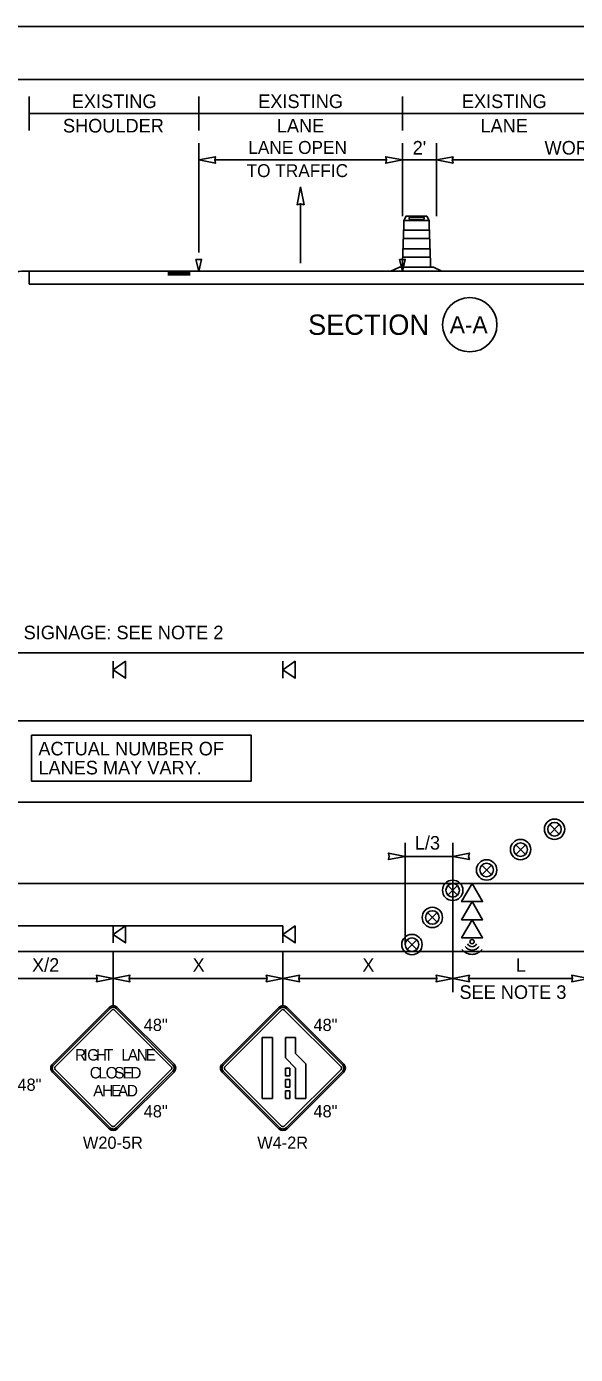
# Model space of a CAD drawing. Extents: x 99999 to 100116, y 99995 to 100013.
# Drawn here: x 100004.26 to 100007.5, y 100002.86 to 100010.69 of the extents above; entities that cross this region are included whole.
import ezdxf

# ---------------------------------------------------------------- set-up
doc = ezdxf.new("R2010")
doc.units = 0
for name, color, linetype in [('RD_ED_ShoulderPavedEdge', 7, 'Continuous'), ('RD_MK_LineEdgeWhite', 7, 'Continuous'), ('RD_MK_LineEdgeYellow', 7, 'Continuous'), ('RD_MK_LineLane', 7, 'Continuous'), ('SH_GI_PlotLimits', 7, 'Continuous'), ('SH_GI_SheetBorder', 7, 'Continuous'), ('SH_TI_Tables', 7, 'Continuous'), ('SH_TI_WZSectionCut', 7, 'Continuous'), ('TR_SN_ConstructionSigns', 7, 'Continuous'), ('TR_WZ_ArrowLeftStrRightTurn', 7, 'Continuous'), ('TR_WZ_PortableSignMountBlk-Org', 7, 'Continuous'), ('TR_WZ_SequentialArrowSign', 7, 'Continuous'), ('TR_WZ_TrafficSafetyDrum', 7, 'Continuous'), ('TR_WZ_TrafficSafetyDrumElev', 7, 'Continuous'), ('TR_WZ_WorkZoneDetails', 7, 'Continuous'), ('TR_WZ_WorkZoneTextCurrent', 7, 'Continuous')]:
    doc.layers.add(name, color=color, linetype=linetype)

msp = doc.modelspace()

# ---------------------------------------------------------------- linework, layer by layer
at = {"layer": 'RD_ED_ShoulderPavedEdge'}
for p, q in [((100000.8283, 100006.9957), (100015.62, 100006.9957)), ((100000.8283, 100005.2357), (100015.62, 100005.2357))]:
    msp.add_line(p, q, dxfattribs=at)
at = {"layer": 'RD_MK_LineEdgeWhite'}
msp.add_line((100000.8283, 100005.6357), (100015.62, 100005.6357), dxfattribs=at)
at = {"layer": 'RD_MK_LineEdgeYellow'}
msp.add_line((100000.8283, 100006.5957), (100015.62, 100006.5957), dxfattribs=at)
at = {"layer": 'RD_MK_LineLane'}
msp.add_lwpolyline([(100015.62, 100006.1157), (100000.8283, 100006.1157)], dxfattribs=at)
at = {"layer": 'SH_GI_PlotLimits'}
msp.add_lwpolyline([(99999.0625, 99999.6875), (100016.0625, 99999.6875), (100016.0625, 100010.6875), (99999.0625, 100010.6875)], close=True, dxfattribs=at)
at = {"layer": 'SH_GI_SheetBorder'}
msp.add_line((100000, 100010.375), (100015.75, 100010.375), dxfattribs=at)
at = {"layer": 'SH_TI_Tables'}
msp.add_lwpolyline([(100004.2941, 100006.511), (100005.5872, 100006.511), (100005.5872, 100006.239), (100004.2941, 100006.239)], close=True, dxfattribs=at)
at = {"layer": 'SH_TI_WZSectionCut'}
for p, q in [((100004.2794, 100010.075), (100004.2794, 100010.275)), ((100005.2794, 100010.075), (100005.2794, 100010.275)), ((100006.4794, 100010.075), (100006.4794, 100010.275)), ((100004.2794, 100010.175), (100005.2794, 100010.175)), ((100005.2794, 100010.175), (100006.4794, 100010.175)), ((100006.4794, 100010.175), (100007.6794, 100010.175)), ((100005.2794, 100009.3547), (100005.2794, 100010.001)), ((100006.4794, 100009.57), (100006.4794, 100010.001)), ((100006.6794, 100009.57), (100006.6794, 100010.001)), ((100005.3731, 100009.901), (100006.3857, 100009.901)), ((100006.4794, 100009.901), (100006.6794, 100009.901)), ((100006.7731, 100009.901), (100008.5857, 100009.901)), ((100004.2794, 100009.2449), (100004.2794, 100009.1699)), ((100008.6794, 100009.2449), (100004.2794, 100009.2449)), ((100005.0964, 100009.2397), (100005.2294, 100009.2397)), ((100005.0964, 100009.2341), (100005.2294, 100009.2341)), ((100005.0964, 100009.2284), (100005.2294, 100009.2284)), ((100008.6794, 100009.1699), (100004.2794, 100009.1699)), ((100005.0964, 100009.2232), (100005.2294, 100009.2232))]:
    msp.add_line(p, q, dxfattribs=at)
for points in [[(100005.2794, 100009.901), (100005.3777, 100009.8817), (100005.3731, 100009.901), (100005.3777, 100009.9203)], [(100006.4794, 100009.901), (100006.3811, 100009.8817), (100006.3857, 100009.901), (100006.3811, 100009.9203)], [(100006.6794, 100009.901), (100006.7777, 100009.8817), (100006.7731, 100009.901), (100006.7777, 100009.9203)], [(100005.2627, 100009.3147), (100005.296, 100009.3147), (100005.2794, 100009.2449)], [(100006.4627, 100009.3147), (100006.4961, 100009.3147), (100006.4794, 100009.2449)]]:
    msp.add_lwpolyline(points, close=True, dxfattribs=at)
msp.add_circle((100006.8759, 100008.93), 0.16, dxfattribs=at)
msp.add_open_spline([(100004.2794, 100009.2449), (100004.0282, 100009.2449), (100003.9027, 100009.1828), (100003.7773, 100009.1828)], degree=2, dxfattribs=at)
at = {"layer": 'TR_SN_ConstructionSigns'}
for p, q in [((100004.7514, 100004.9058), (100004.4173, 100004.5717)), ((100004.7574, 100004.8999), (100004.4233, 100004.5658)), ((100004.4332, 100004.5558), (100004.7673, 100004.8899)), ((100004.7832, 100004.8899), (100005.1173, 100004.5558)), ((100005.1273, 100004.5658), (100004.7932, 100004.8999)), ((100005.1333, 100004.5717), (100004.7991, 100004.9058)), ((100005.7514, 100004.9058), (100005.4173, 100004.5717)), ((100005.7574, 100004.8999), (100005.4233, 100004.5658)), ((100005.4332, 100004.5558), (100005.7673, 100004.8899)), ((100005.7832, 100004.8899), (100006.1173, 100004.5558)), ((100006.1273, 100004.5658), (100005.7932, 100004.8999)), ((100006.1333, 100004.5717), (100005.7991, 100004.9058)), ((100005.6536, 100004.7279), (100005.7141, 100004.7279)), ((100005.6536, 100004.3679), (100005.6536, 100004.7279)), ((100005.7141, 100004.7279), (100005.6536, 100004.7279)), ((100005.6536, 100004.7279), (100005.6536, 100004.3679)), ((100005.7141, 100004.7279), (100005.7141, 100004.3679)), ((100005.7141, 100004.3679), (100005.7141, 100004.7279)), ((100005.7893, 100004.7279), (100005.8498, 100004.7279)), ((100005.7893, 100004.6083), (100005.7893, 100004.7279)), ((100005.8498, 100004.7279), (100005.7893, 100004.7279)), ((100005.7893, 100004.7279), (100005.7893, 100004.6083)), ((100005.8498, 100004.7279), (100005.8498, 100004.6334)), ((100005.8498, 100004.6334), (100005.8498, 100004.7279)), ((100005.8498, 100004.6334), (100005.9103, 100004.5729)), ((100005.9103, 100004.5729), (100005.8498, 100004.6334)), ((100004.7673, 100004.2058), (100004.4332, 100004.5399)), ((100005.1173, 100004.5399), (100004.7832, 100004.2058)), ((100005.7673, 100004.2058), (100005.4332, 100004.5399)), ((100006.1173, 100004.5399), (100005.7832, 100004.2058)), ((100005.8498, 100004.5479), (100005.7893, 100004.6083)), ((100005.7893, 100004.6083), (100005.8498, 100004.5479)), ((100005.7893, 100004.5479), (100005.8161, 100004.5479)), ((100005.7893, 100004.5029), (100005.7893, 100004.5479)), ((100005.8161, 100004.5479), (100005.7893, 100004.5479)), ((100005.7893, 100004.5479), (100005.7893, 100004.5029)), ((100005.8161, 100004.5479), (100005.8161, 100004.5029)), ((100005.8161, 100004.5029), (100005.8161, 100004.5479)), ((100005.8498, 100004.3679), (100005.8498, 100004.5479)), ((100005.8498, 100004.5479), (100005.8498, 100004.3679)), ((100005.9103, 100004.5729), (100005.9103, 100004.3679)), ((100005.9103, 100004.3679), (100005.9103, 100004.5729)), ((100004.4173, 100004.524), (100004.7514, 100004.1899)), ((100004.4233, 100004.53), (100004.7574, 100004.1959)), ((100004.7932, 100004.1959), (100005.1273, 100004.53)), ((100004.7991, 100004.1899), (100005.1333, 100004.524)), ((100005.4173, 100004.524), (100005.7514, 100004.1899)), ((100005.4233, 100004.53), (100005.7574, 100004.1959)), ((100005.8161, 100004.5029), (100005.7893, 100004.5029)), ((100005.7893, 100004.5029), (100005.8161, 100004.5029)), ((100005.7893, 100004.4804), (100005.8161, 100004.4804)), ((100005.7893, 100004.4354), (100005.7893, 100004.4804)), ((100005.8161, 100004.4804), (100005.7893, 100004.4804)), ((100005.7893, 100004.4804), (100005.7893, 100004.4354)), ((100005.7932, 100004.1959), (100006.1273, 100004.53)), ((100005.7991, 100004.1899), (100006.1333, 100004.524)), ((100005.8161, 100004.4804), (100005.8161, 100004.4354)), ((100005.8161, 100004.4354), (100005.8161, 100004.4804)), ((100005.8161, 100004.4354), (100005.7893, 100004.4354)), ((100005.7893, 100004.4354), (100005.8161, 100004.4354)), ((100005.7893, 100004.4129), (100005.8161, 100004.4129)), ((100005.7893, 100004.3679), (100005.7893, 100004.4129)), ((100005.8161, 100004.4129), (100005.7893, 100004.4129)), ((100005.7893, 100004.4129), (100005.7893, 100004.3679)), ((100005.8161, 100004.4129), (100005.8161, 100004.3679)), ((100005.8161, 100004.3679), (100005.8161, 100004.4129)), ((100005.7141, 100004.3679), (100005.6536, 100004.3679)), ((100005.6536, 100004.3679), (100005.7141, 100004.3679)), ((100005.8161, 100004.3679), (100005.7893, 100004.3679)), ((100005.7893, 100004.3679), (100005.8161, 100004.3679)), ((100005.9103, 100004.3679), (100005.8498, 100004.3679)), ((100005.8498, 100004.3679), (100005.9103, 100004.3679))]:
    msp.add_line(p, q, dxfattribs=at)
for centre, radius, start, end in [((100004.7753, 100004.882), 0.0338, 45, 135), ((100004.7753, 100004.882), 0.0253, 45, 135), ((100004.7753, 100004.882), 0.0113, 45, 135), ((100005.7753, 100004.882), 0.0338, 45, 135), ((100005.7753, 100004.882), 0.0253, 45, 135), ((100005.7753, 100004.882), 0.0113, 45, 135), ((100004.4412, 100004.5479), 0.0338, 135, 225.00001), ((100004.4412, 100004.5479), 0.0253, 135, 225.00001), ((100004.4412, 100004.5479), 0.0113, 135, 225.00001), ((100005.1094, 100004.5479), 0.0113, 315.00002, 45), ((100005.1094, 100004.5479), 0.0253, 315.00002, 45), ((100005.1094, 100004.5479), 0.0338, 315.00001, 45.00001), ((100005.4412, 100004.5479), 0.0338, 135, 225.00001), ((100005.4412, 100004.5479), 0.0253, 135, 225.00001), ((100005.4412, 100004.5479), 0.0113, 135, 225.00001), ((100006.1094, 100004.5479), 0.0113, 315.00002, 45), ((100006.1094, 100004.5479), 0.0253, 315.00002, 45), ((100006.1094, 100004.5479), 0.0338, 315.00001, 45.00001), ((100004.7753, 100004.2138), 0.0338, 225.00001, 315.00001), ((100004.7753, 100004.2138), 0.0253, 225.00001, 315.00002), ((100004.7753, 100004.2138), 0.0113, 225.00001, 315.00002), ((100005.7753, 100004.2138), 0.0338, 225.00001, 315.00001), ((100005.7753, 100004.2138), 0.0253, 225.00001, 315.00002), ((100005.7753, 100004.2138), 0.0113, 225.00001, 315.00002)]:
    msp.add_arc(centre, radius, start, end, dxfattribs=at)
at = {"layer": 'TR_WZ_ArrowLeftStrRightTurn'}
msp.add_line((100005.8794, 100009.6418), (100005.8794, 100009.292), dxfattribs=at)
msp.add_lwpolyline([(100005.8794, 100009.742), (100005.8588, 100009.6369), (100005.8794, 100009.6418), (100005.9, 100009.6369)], close=True, dxfattribs=at)
at = {"layer": 'TR_WZ_PortableSignMountBlk-Org'}
for p, q in [((100004.7753, 100006.8458), (100004.7753, 100006.9458)), ((100005.7753, 100006.8458), (100005.7753, 100006.9458)), ((100004.7753, 100005.2858), (100004.7753, 100005.3858)), ((100005.7753, 100005.2858), (100005.7753, 100005.3858))]:
    msp.add_line(p, q, dxfattribs=at)
for points in [[(100004.7753, 100006.8957), (100004.8471, 100006.9458), (100004.8471, 100006.8458)], [(100005.7753, 100006.8957), (100005.8471, 100006.9458), (100005.8471, 100006.8458)], [(100004.7753, 100005.3357), (100004.8471, 100005.3858), (100004.8471, 100005.2858)], [(100005.7753, 100005.3357), (100005.8471, 100005.3858), (100005.8471, 100005.2858)]]:
    msp.add_lwpolyline(points, close=True, dxfattribs=at)
at = {"layer": 'TR_WZ_SequentialArrowSign'}
for points in [[(100006.8895, 100005.6357), (100006.8278, 100005.5291), (100006.8895, 100005.5291), (100006.9513, 100005.5291), (100006.8895, 100005.6357)], [(100006.9513, 100005.5291), (100006.8895, 100005.5291), (100006.8278, 100005.5291), (100006.8895, 100005.6357), (100006.9513, 100005.5291)], [(100006.8895, 100005.5291), (100006.8278, 100005.4224), (100006.8895, 100005.4224), (100006.9513, 100005.4224), (100006.8895, 100005.5291)], [(100006.9513, 100005.4224), (100006.8895, 100005.4224), (100006.8278, 100005.4224), (100006.8895, 100005.5291), (100006.9513, 100005.4224)], [(100006.8895, 100005.4224), (100006.8278, 100005.3157), (100006.9513, 100005.3157), (100006.8895, 100005.4224)], [(100006.9513, 100005.3157), (100006.8278, 100005.3157), (100006.8895, 100005.4224), (100006.9513, 100005.3157)]]:
    msp.add_lwpolyline(points, dxfattribs=at)
msp.add_circle((100006.8895, 100005.2932), 0.0125, dxfattribs=at)
for radius, start, end in [(0.075, 217.32912, 322.67088), (0.05, 213.97816, 326.02184), (0.03, 207.15796, 332.84204)]:
    msp.add_arc((100006.8895, 100005.2932), radius, start, end, dxfattribs=at)
at = {"layer": 'TR_WZ_TrafficSafetyDrum'}
for p, q in [((100007.347, 100005.984), (100007.4036, 100005.9274)), ((100007.4036, 100005.984), (100007.347, 100005.9274)), ((100007.147, 100005.864), (100007.2036, 100005.8074)), ((100007.2036, 100005.864), (100007.147, 100005.8074)), ((100006.947, 100005.744), (100007.0036, 100005.6874)), ((100007.0036, 100005.744), (100006.947, 100005.6874)), ((100006.747, 100005.624), (100006.8036, 100005.5674)), ((100006.8036, 100005.624), (100006.747, 100005.5674)), ((100006.627, 100005.464), (100006.6836, 100005.4074)), ((100006.6836, 100005.464), (100006.627, 100005.4074)), ((100006.507, 100005.304), (100006.5636, 100005.2474)), ((100006.5636, 100005.304), (100006.507, 100005.2474))]:
    msp.add_line(p, q, dxfattribs=at)
for centre, radius in [((100007.3753, 100005.9557), 0.06), ((100007.3753, 100005.9557), 0.06), ((100007.3753, 100005.9557), 0.04), ((100007.1753, 100005.8357), 0.06), ((100007.1753, 100005.8357), 0.06), ((100007.1753, 100005.8357), 0.04), ((100006.9753, 100005.7157), 0.06), ((100006.9753, 100005.7157), 0.06), ((100006.9753, 100005.7157), 0.04), ((100006.7753, 100005.5957), 0.06), ((100006.7753, 100005.5957), 0.06), ((100006.7753, 100005.5957), 0.04), ((100006.6553, 100005.4357), 0.06), ((100006.6553, 100005.4357), 0.06), ((100006.6553, 100005.4357), 0.04), ((100006.5353, 100005.2757), 0.06), ((100006.5353, 100005.2757), 0.06), ((100006.5353, 100005.2757), 0.04)]:
    msp.add_circle(centre, radius, dxfattribs=at)
at = {"layer": 'TR_WZ_TrafficSafetyDrumElev'}
for p, q in [((100006.4878, 100009.545), (100006.6358, 100009.545)), ((100006.4878, 100009.545), (100006.6358, 100009.545)), ((100006.5222, 100009.564), (100006.604, 100009.564)), ((100006.604, 100009.551), (100006.5222, 100009.551)), ((100006.4849, 100009.4871), (100006.6386, 100009.4871)), ((100006.4849, 100009.4372), (100006.4849, 100009.4871)), ((100006.6386, 100009.4871), (100006.6386, 100009.4372)), ((100006.6386, 100009.4372), (100006.4849, 100009.4372)), ((100006.4812, 100009.377), (100006.6423, 100009.377)), ((100006.4812, 100009.3271), (100006.4812, 100009.377)), ((100006.6423, 100009.3271), (100006.4812, 100009.3271)), ((100006.6423, 100009.377), (100006.6423, 100009.3271))]:
    msp.add_line(p, q, dxfattribs=at)
for points in [[(100006.4868, 100009.4915), (100006.4868, 100009.543)], [(100006.4868, 100009.4915), (100006.4868, 100009.543)], [(100006.6368, 100009.543), (100006.6368, 100009.4915)], [(100006.6368, 100009.543), (100006.6368, 100009.4915)], [(100006.4849, 100009.4365), (100006.4849, 100009.4878)], [(100006.4849, 100009.4365), (100006.4849, 100009.4878)], [(100006.6386, 100009.4878), (100006.6386, 100009.4365)], [(100006.6386, 100009.4878), (100006.6386, 100009.4365)], [(100006.4831, 100009.3814), (100006.4831, 100009.4327)], [(100006.4831, 100009.3814), (100006.4831, 100009.4327)], [(100006.6405, 100009.4327), (100006.6405, 100009.3814)], [(100006.6405, 100009.4327), (100006.6405, 100009.3814)], [(100006.6442, 100009.3226), (100006.6442, 100009.27), (100006.4794, 100009.27), (100006.4794, 100009.3226)], [(100006.6442, 100009.3226), (100006.6442, 100009.27), (100006.4794, 100009.27), (100006.4794, 100009.3226)], [(100006.4812, 100009.3264), (100006.4812, 100009.3777)], [(100006.4812, 100009.3264), (100006.4812, 100009.3777)], [(100006.6423, 100009.3777), (100006.6423, 100009.3264)], [(100006.6423, 100009.3777), (100006.6423, 100009.3264)]]:
    msp.add_lwpolyline(points, dxfattribs=at)
for points in [[(100006.6358, 100009.545), (100006.6226, 100009.57), (100006.5009, 100009.57), (100006.4878, 100009.545)], [(100006.4118, 100009.245), (100006.462, 100009.27), (100006.6615, 100009.27), (100006.7118, 100009.245)]]:
    msp.add_lwpolyline(points, close=True, dxfattribs=at)
for centre, major_axis, ratio, start_param, end_param in [((100006.488, 100009.5426), (0, 0.00249), 0.493438, 0.177149, 1.393647), ((100006.488, 100009.5426), (0, 0.00249), 0.493438, 0.177149, 1.393647), ((100006.5222, 100009.5575), (0, 0.0065), 0.570305, 0, 3.141593), ((100006.604, 100009.5575), (0, 0.0065), 0.570305, 3.141593, 6.283185), ((100006.6356, 100009.5426), (0, 0.00249), 0.493438, 4.889538, 6.106036), ((100006.6356, 100009.5426), (0, 0.00249), 0.493438, 4.889538, 6.106036), ((100006.4883, 100009.4846), (0, 0.00758), 0.493438, 0.4288, 1.141997), ((100006.4883, 100009.4846), (0, 0.00758), 0.493438, 0.4288, 1.141997), ((100006.6352, 100009.4846), (0, 0.00758), 0.493438, 5.141189, 5.854386), ((100006.6352, 100009.4846), (0, 0.00758), 0.493438, 5.141189, 5.854386), ((100006.4865, 100009.4296), (0, 0.00758), 0.493438, 0.4288, 1.141997), ((100006.4865, 100009.4296), (0, 0.00758), 0.493438, 0.4288, 1.141997), ((100006.6371, 100009.4296), (0, 0.00758), 0.493438, 5.141189, 5.854386), ((100006.6371, 100009.4296), (0, 0.00758), 0.493438, 5.141189, 5.854386), ((100006.4828, 100009.3195), (0, 0.00758), 0.493438, 0.4288, 1.141997), ((100006.4828, 100009.3195), (0, 0.00758), 0.493438, 0.4288, 1.141997), ((100006.4846, 100009.3745), (0, 0.00758), 0.493438, 0.4288, 1.141997), ((100006.4846, 100009.3745), (0, 0.00758), 0.493438, 0.4288, 1.141997), ((100006.6389, 100009.3745), (0, 0.00758), 0.493438, 5.141189, 5.854386), ((100006.6389, 100009.3745), (0, 0.00758), 0.493438, 5.141189, 5.854386), ((100006.6408, 100009.3195), (0, 0.00758), 0.493438, 5.141189, 5.854386), ((100006.6408, 100009.3195), (0, 0.00758), 0.493438, 5.141189, 5.854386)]:
    msp.add_ellipse(centre, major_axis=major_axis, ratio=ratio, start_param=start_param, end_param=end_param, dxfattribs=at)
at = {"layer": 'TR_WZ_WorkZoneDetails'}
for p, q in [((100006.4953, 100005.8757), (100006.4953, 100005.2757)), ((100006.7753, 100005.8757), (100006.7753, 100004.9957)), ((100006.7753, 100005.7957), (100006.4953, 100005.7957)), ((100003.1753, 100005.3858), (100005.7753, 100005.3858)), ((100004.7753, 100005.236), (100004.7753, 100004.9157)), ((100005.7753, 100005.236), (100005.7753, 100004.9157)), ((100004.6815, 100005.0757), (100004.069, 100005.0757)), ((100005.6815, 100005.0757), (100004.869, 100005.0757)), ((100006.6815, 100005.0757), (100005.869, 100005.0757)), ((100007.4815, 100005.0757), (100006.869, 100005.0757))]:
    msp.add_line(p, q, dxfattribs=at)
for points in [[(100006.4953, 100005.7957), (100006.397, 100005.7765), (100006.4016, 100005.7957), (100006.397, 100005.815)], [(100006.7753, 100005.7957), (100006.8736, 100005.7765), (100006.869, 100005.7957), (100006.8736, 100005.815)], [(100004.7753, 100005.0757), (100004.677, 100005.095), (100004.6815, 100005.0757), (100004.677, 100005.0565)], [(100004.7753, 100005.0757), (100004.8736, 100005.095), (100004.869, 100005.0757), (100004.8736, 100005.0565)], [(100005.7753, 100005.0757), (100005.677, 100005.095), (100005.6815, 100005.0757), (100005.677, 100005.0565)], [(100005.7753, 100005.0757), (100005.8736, 100005.095), (100005.869, 100005.0757), (100005.8736, 100005.0565)], [(100006.7753, 100005.0757), (100006.677, 100005.095), (100006.6815, 100005.0757), (100006.677, 100005.0565)], [(100006.7753, 100005.0757), (100006.8736, 100005.095), (100006.869, 100005.0757), (100006.8736, 100005.0565)], [(100007.5753, 100005.0757), (100007.477, 100005.095), (100007.4815, 100005.0757), (100007.477, 100005.0565)]]:
    msp.add_lwpolyline(points, close=True, dxfattribs=at)

# ---------------------------------------------------------------- texts
at = {"layer": 'SH_TI_Tables'}
for s, p in [('ACTUAL NUMBER OF', (100004.3341, 100006.391)), ('LANES MAY VARY.', (100004.3341, 100006.279))]:
    msp.add_text(s, height=0.08, rotation=360, dxfattribs=at).set_placement(p)
at = {"layer": 'SH_TI_WZSectionCut'}
for s, height, p in [('EXISTING', 0.08, (100004.5311, 100010.207)), ('EXISTING', 0.08, (100005.6296, 100010.207)), ('EXISTING', 0.08, (100006.8296, 100010.207)), ('SHOULDER', 0.08, (100004.4792, 100010.063)), ('LANE', 0.08, (100005.739, 100010.063)), ('LANE', 0.08, (100006.939, 100010.063)), ('SECTION', 0.12, (100005.9229, 100008.87)), ('A-A', 0.1, (100006.7581, 100008.88))]:
    msp.add_text(s, height=height, rotation=360, dxfattribs=at).set_placement(p)
for s, height, p in [('LANE OPEN', 0.076, (100005.5707, 100009.937)), ("2'", 0.08, (100006.5394, 100009.933)), ('WORK AREA', 0.08, (100007.3165, 100009.933)), ('TO TRAFFIC', 0.076, (100005.5606, 100009.8002))]:
    msp.add_text(s, height=height, dxfattribs=at).set_placement(p)
at = {"layer": 'TR_SN_ConstructionSigns'}
for s, p in [('48"', (100004.9551, 100004.7664)), ('48"', (100005.9551, 100004.7664)), ('48"', (100004.211, 100004.414)), ('48"', (100004.9551, 100004.2573)), ('48"', (100005.9551, 100004.2573)), ('W20-5R', (100004.5966, 100004.072)), ('W4-2R', (100005.6238, 100004.072))]:
    msp.add_text(s, height=0.072, rotation=360, dxfattribs=at).set_placement(p)
for s, p in [('R', (100004.5498, 100004.5922)), ('I', (100004.5991, 100004.5922)), ('G', (100004.6221, 100004.5922)), ('H', (100004.6734, 100004.5922)), ('T', (100004.7206, 100004.5922)), ('L', (100004.8225, 100004.5922)), ('A', (100004.861, 100004.5922)), ('N', (100004.9137, 100004.5922)), ('E', (100004.9663, 100004.5922)), ('C', (100004.6369, 100004.4867)), ('L', (100004.6882, 100004.4867)), ('O', (100004.7307, 100004.4867)), ('S', (100004.7807, 100004.4867)), ('E', (100004.83, 100004.4867)), ('D', (100004.8759, 100004.4867)), ('A', (100004.6572, 100004.3812)), ('H', (100004.7098, 100004.3812)), ('E', (100004.7625, 100004.3812)), ('A', (100004.803, 100004.3812)), ('D', (100004.8556, 100004.3812))]:
    msp.add_text(s, height=0.0675, dxfattribs=at).set_placement(p)
at = {"layer": 'TR_WZ_WorkZoneTextCurrent'}
for s, p in [('LEFT SHOULDER SIGNAGE: SEE NOTE 2', (100003.3319, 100007.0757)), ('L/3', (100006.5521, 100005.8357))]:
    msp.add_text(s, height=0.08, dxfattribs=at).set_placement(p)
for s, p in [('X/2', (100004.2968, 100005.1157)), ('X', (100005.2428, 100005.1157)), ('X', (100006.2428, 100005.1157)), ('L', (100007.1481, 100005.1157)), ('SEE NOTE 3', (100006.8151, 100004.9557))]:
    msp.add_text(s, height=0.08, rotation=360, dxfattribs=at).set_placement(p)

doc.saveas('drawing.dxf')
